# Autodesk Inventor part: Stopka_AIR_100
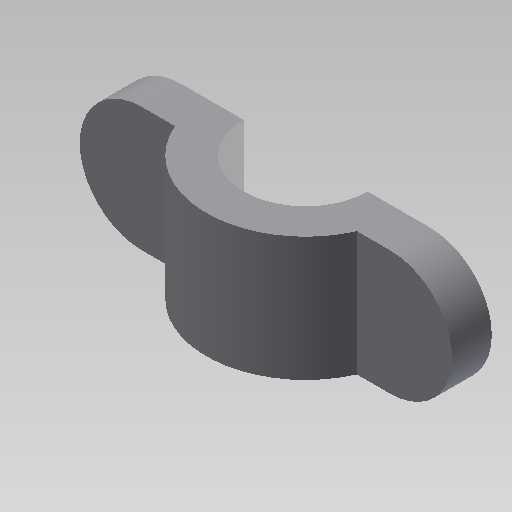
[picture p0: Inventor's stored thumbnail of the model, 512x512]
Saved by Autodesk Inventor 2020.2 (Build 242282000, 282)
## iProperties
Created: 2014-10
Part Number: Stopka_AIR_100
Material: Ogólny
Document SubType Name: Modeling
Designer: F.Stasiak
Density: 1 g/cm^3
Appearance: Domyślna
Catalog Web Link: www.expertbooks.pl
Manager: www.cadconsulting.pl
Company: Fabian Stasiak CAD Consulting
Author: F.Stasiak
Subject: Zbiór ćwiczeń. Autodesk Inventor 2020. Kurs Professional
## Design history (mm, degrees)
sketch "Szkic1"
  geometry: L1 (0, 12.5)-(12.5, 12.5) reference; L2 (0, -12.5)-(0, 12.5) reference; L3 (0, -12.5)-(12.5, -12.5) reference; L4 (-25, -12.5)-(-25, 12.5) reference; L5 (-37.5, 12.5)-(-25, 12.5) reference; L6 (-25, -12.5)-(-37.5, -12.5) reference; A1 r 12.5 centre (12.5, 0) between (12.5, -12.5) and (12.5, 12.5) reference; A2 r 12.5 centre (-37.5, 0) between (-37.5, 12.5) and (-37.5, -12.5) reference; 1 further point
extrude "Wyciągnięcie proste1" new body sketch "Szkic1" distance "d0" = 8; taper "d1" = 0 deg
sketch "Szkic2"
  geometry: L1 (32.5, 0)-(-7.5, 0); A1 r 12.5 centre (12.5, 0) between (0, 0) and (25, 0) reference; A2 r 12.5 centre (12.5, 0) between (25, 0) and (0, 0); A3 r 20 centre (12.5, 0) between (32.5, 0) and (-7.5, 0)
  constraints: 4 point on circle, 2 centre point, 2 coincident, 2 end point, 2 point on line, 1 horizontal
  dimensions: "d2" = 40 diameter of A3
extrude "Wyciągnięcie proste2" join sketch "Szkic2" stored distance "d3" = 25; taper "d4" = 0 deg
node "Bryła1"
node "Odniesienie1"
node "Odniesienie2"
node "Odniesienie3"
